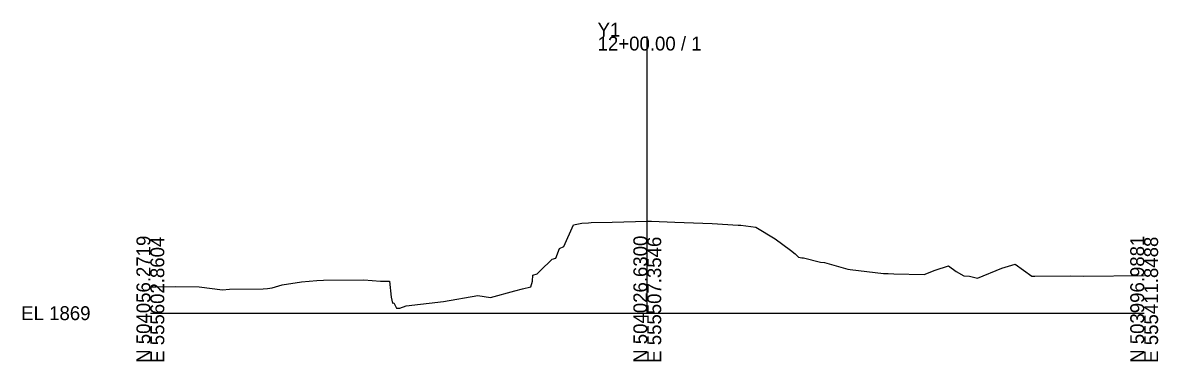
# Model space of a CAD drawing. Extents: x -26 to 203, y -10 to 5015.
# Drawn here: x -25.7 to 202.8, y 1990.3 to 2058.5 of the extents above; entities that cross this region are included whole.
import ezdxf

# ---------------------------------------------------------------- set-up
doc = ezdxf.new("R2010")
doc.units = 0
doc.layers.add('Exist Cross Section Cell', color=7, linetype='Continuous')
doc.layers.add('Exist XS Ground Line', color=7, linetype='Continuous')

msp = doc.modelspace()

# ---------------------------------------------------------------- linework, layer by layer
at = {"layer": 'Exist Cross Section Cell'}
for p, q in [((100, 2000), (100, 2055.69)), ((0, 2000), (100, 2000)), ((100, 2000), (200, 2000))]:
    msp.add_line(p, q, dxfattribs=at)
at = {"layer": 'Exist XS Ground Line'}
for p, q in [((85.17, 2017.8), (86.8, 2018.1)), ((86.8, 2018.1), (88.17, 2018.18)), ((88.17, 2018.18), (88.69, 2018.23)), ((88.69, 2018.23), (92.93, 2018.3)), ((92.93, 2018.3), (100, 2018.54)), ((100, 2018.54), (100.86, 2018.56)), ((100.86, 2018.56), (105.52, 2018.33)), ((105.52, 2018.33), (113.05, 2018.04)), ((113.05, 2018.04), (118.32, 2017.74)), ((83.2, 2013.4), (85.17, 2017.8)), ((118.32, 2017.74), (118.83, 2017.7)), ((118.83, 2017.7), (121.87, 2017.31)), ((121.87, 2017.31), (125.73, 2014.95)), ((82.35, 2013.04), (83.2, 2013.4)), ((125.73, 2014.95), (128.85, 2012.72)), ((80.85, 2010.85), (81.61, 2011.1)), ((81.61, 2011.1), (82.35, 2013.04)), ((128.85, 2012.72), (129.74, 2011.92)), ((129.74, 2011.92), (130.43, 2011.29)), ((130.43, 2011.29), (131.11, 2011.16)), ((131.11, 2011.16), (131.44, 2011.11)), ((131.44, 2011.11), (134.84, 2010.28)), ((78.45, 2008.52), (80.85, 2010.85)), ((134.84, 2010.28), (135.64, 2010.19)), ((135.64, 2010.19), (139.87, 2009.01)), ((139.87, 2009.01), (140.37, 2008.83)), ((140.37, 2008.83), (140.85, 2008.8)), ((157.97, 2008.69), (160.65, 2009.51)), ((160.65, 2009.51), (162.14, 2008.41)), ((166.43, 2007.05), (171.38, 2009.07)), ((171.38, 2009.07), (174.02, 2009.86)), ((174.02, 2009.86), (177.42, 2007.47)), ((30.38, 2006.32), (33.49, 2006.59)), ((33.49, 2006.59), (34.87, 2006.62)), ((34.87, 2006.62), (42.99, 2006.74)), ((42.99, 2006.74), (46.33, 2006.43)), ((76.92, 2006.43), (76.98, 2007.64)), ((76.98, 2007.64), (77.82, 2007.91)), ((77.82, 2007.91), (78.45, 2008.52)), ((140.85, 2008.8), (147.54, 2007.97)), ((147.54, 2007.97), (148.46, 2007.96)), ((148.46, 2007.96), (149.64, 2007.9)), ((149.64, 2007.9), (155.73, 2007.79)), ((155.73, 2007.79), (157.97, 2008.69)), ((162.14, 2008.41), (163.68, 2007.5)), ((163.68, 2007.5), (164.87, 2007.42)), ((164.87, 2007.42), (166.43, 2007.05)), ((177.42, 2007.47), (178.02, 2007.47)), ((178.02, 2007.47), (185.1, 2007.53)), ((185.1, 2007.53), (187.75, 2007.48)), ((187.75, 2007.48), (200, 2007.56)), ((0, 2005.29), (1.14, 2005.29)), ((1.14, 2005.29), (5.12, 2005.35)), ((5.12, 2005.35), (9.8, 2005.27)), ((9.8, 2005.27), (14.49, 2004.72)), ((14.49, 2004.72), (15.95, 2004.81)), ((15.95, 2004.81), (22.68, 2004.92)), ((22.68, 2004.92), (23.54, 2005)), ((23.54, 2005), (24.51, 2005.1)), ((24.51, 2005.1), (26.54, 2005.73)), ((26.54, 2005.73), (30.38, 2006.32)), ((46.33, 2006.43), (46.86, 2006.43)), ((46.86, 2006.43), (47.28, 2006.46)), ((47.28, 2006.46), (48.14, 2006.47)), ((48.14, 2006.47), (48.44, 2003.22)), ((68.46, 2003.13), (73.35, 2004.47)), ((73.35, 2004.47), (74.87, 2004.88)), ((74.87, 2004.88), (76.56, 2005.27)), ((76.56, 2005.27), (76.92, 2006.43)), ((48.44, 2003.22), (48.74, 2002)), ((48.74, 2002), (48.97, 2002.07)), ((48.97, 2002.07), (49.54, 2001.03)), ((51.47, 2001.51), (59.01, 2002.36)), ((59.01, 2002.36), (65.89, 2003.55)), ((65.89, 2003.55), (68.46, 2003.13)), ((49.54, 2001.03), (50.22, 2000.99)), ((50.22, 2000.99), (51.47, 2001.51))]:
    msp.add_line(p, q, dxfattribs=at)

# ---------------------------------------------------------------- texts
at = {"layer": 'Exist Cross Section Cell'}
for s, p in [('Y1', (90, 2055.69)), ('12+00.00 / 1', (90, 2052.89)), ('EL 1869', (-26, 1998.6))]:
    msp.add_text(s, height=2.8, dxfattribs=at).set_placement(p)
for s, p in [('N 504056.2719', (0, 1990)), ('E 555602.8604', (2.8, 1990)), ('N 504026.6300', (100, 1990)), ('E 555507.3546', (102.8, 1990)), ('N 503996.9881', (200, 1990)), ('E 555411.8488', (202.8, 1990))]:
    msp.add_text(s, height=2.8, rotation=90, dxfattribs=at).set_placement(p)

doc.saveas('drawing.dxf')
